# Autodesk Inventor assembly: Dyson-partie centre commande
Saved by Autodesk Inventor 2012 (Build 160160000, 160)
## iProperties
Created: 2012-11
Part Number: Dyson-partie centre commande
Document SubType Name: Assembly
Designer: Administrateur
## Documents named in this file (11)
- F:\Dyson\SI\2_Présentation éleve\SW_AM01 complet\Composants importés\Dyson Air Multiplier-Assemblage final\Dyson-partie centre commande.iam
- F:\Dyson\SI\2_Présentation éleve\SW_AM01 complet\Composants importés\Dyson Air Multiplier-Assemblage final\Dyson-Partie centre commande.ipt
- F:\Dyson\SI\2_Présentation éleve\SW_AM01 complet\Composants importés\Dyson Air Multiplier-Assemblage final\Dyson-Partie centre support commande.ipt
- F:\Dyson\SI\2_Présentation éleve\SW_AM01 complet\Composants importés\Dyson Air Multiplier-Assemblage final\Vis torks M2x6.ipt
- F:\Dyson\SI\2_Présentation éleve\SW_AM01 complet\Composants importés\Dyson Air Multiplier-Assemblage final\Dyson-Partie centre Ci commande.ipt
- F:\Dyson\SI\2_Présentation éleve\SW_AM01 complet\Composants importés\Dyson Air Multiplier-Assemblage final\Dyson-Partie centre liaison.ipt
- F:\Dyson\SI\2_Présentation éleve\SW_AM01 complet\Composants importés\Dyson Air Multiplier-Assemblage final\Dyson-Partie centre cylindre filtration.ipt
- F:\Dyson\SI\2_Présentation éleve\SW_AM01 complet\Composants importés\Dyson Air Multiplier-Assemblage final\Dyson-Partie centre joint noir.ipt
- F:\Dyson\SI\2_Présentation éleve\SW_AM01 complet\Composants importés\Dyson Air Multiplier-Assemblage final\Dyson-Partie centre cylindre mousse.ipt
- F:\Dyson\SI\2_Présentation éleve\SW_AM01 complet\Composants importés\Dyson Air Multiplier-Assemblage final\Dyson-partie centre motorisation.iam
- F:\Dyson\SI\2_Présentation éleve\SW_AM01 complet\Composants importés\Dyson Air Multiplier-Assemblage final\Dyson-Partie inf. cercle ABS noir.ipt
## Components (14 placed, 10 different names)
1. Dyson-Partie centre commande:1
2. Dyson-Partie centre support commande:1
3. Vis torks M2x6:1
4. Vis torks M2x6:2
5. Dyson-Partie centre Ci commande:1
6. Vis torks M2x6:3
7. Vis torks M2x6:4
8. Vis torks M2x6:5
9. Dyson-Partie centre liaison:1
10. Dyson-Partie centre cylindre filtration:1
11. Dyson-Partie centre joint noir:1
12. Dyson-Partie centre cylindre mousse:1
13. Dyson-partie centre motorisation:1 [sub-assembly]
14. Dyson-Partie inf. cercle ABS noir:1
